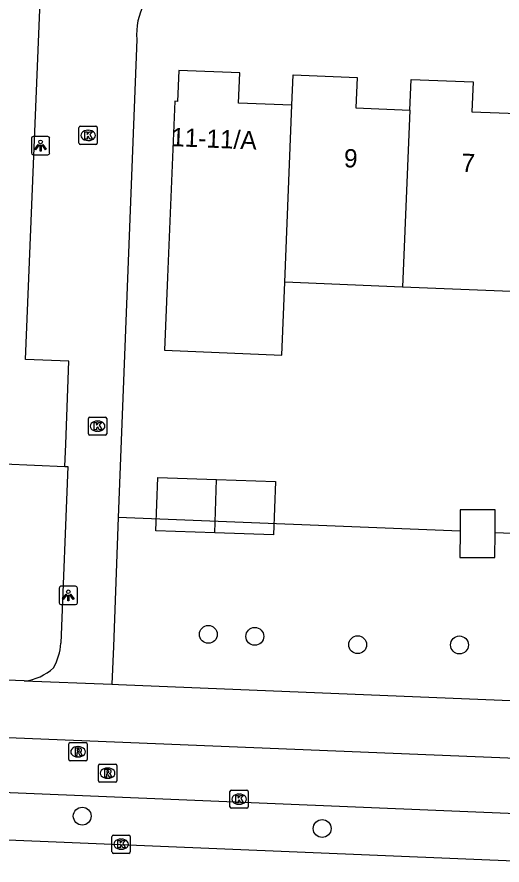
# Model space of a CAD drawing. Extents: x 160732 to 162105, y 387428 to 388479.
# Drawn here: x 161101.46 to 161128, y 387478.56 to 387524.95 of the extents above; entities that cross this region are included whole.
import ezdxf

# ---------------------------------------------------------------- set-up
doc = ezdxf.new("R2010")
doc.units = 0
for name, color, linetype in [('IMGEO_Boom', 7, 'Continuous'), ('IMGEO_Fietspad_open', 7, 'Continuous'), ('IMGEO_Groenvoorziening', 7, 'Continuous'), ('IMGEO_Kolk', 7, 'Continuous'), ('IMGEO_Lichtpunt', 7, 'Continuous'), ('IMGEO_Pand', 7, 'Continuous'), ('IMGEO_Pand_nummerreeks', 7, 'Continuous'), ('IMGEO_Pand_vergunning_verleend', 7, 'Continuous'), ('IMGEO_Rijbaan_lokaal_gesloten', 7, 'Continuous'), ('IMGEO_Rioolput', 7, 'Continuous'), ('IMGEO_Voetpad_open', 7, 'Continuous')]:
    doc.layers.add(name, color=color, linetype=linetype)

msp = doc.modelspace()

# ---------------------------------------------------------------- linework, layer by layer
at = {"layer": 'IMGEO_Boom'}
for centre in [(161111.928, 387491.176), (161114.47, 387491.066), (161120.1, 387490.611), (161125.67, 387490.598), (161105.028, 387481.234), (161118.157, 387480.553)]:
    msp.add_circle(centre, 0.489, dxfattribs=at)
at = {"layer": 'IMGEO_Fietspad_open'}
for points in [[(160801.558, 387514.26), (160820.517, 387511.401), (160862.38, 387504.81), (160891.554, 387500.319), (160901.233, 387498.754), (160911.562, 387497.191), (160935.793, 387493.329), (160945.905, 387492.112), (160955.896, 387491.483), (160964.882, 387491.216), (161000, 387489.783), (161032.946, 387488.45), (161079.41, 387486.41), (161134.151, 387484.191)], [(161032.863, 387485.379), (161078.213, 387483.477), (161134.039, 387481.162)]]:
    msp.add_lwpolyline(points, dxfattribs=at)
at = {"layer": 'IMGEO_Groenvoorziening'}
for points in [[(161070.371, 387540.152), (161070.05, 387531.608), (161068.211, 387531.677), (161067.968, 387525.152), (161069.806, 387525.083), (161068.983, 387503.133), (161068.831, 387499.085), (161090.674, 387498.116), (161090.78, 387500.95), (161104.081, 387500.36)], [(161125.701, 387496.813), (161107.002, 387497.56)], [(161149.999, 387495.842), (161127.619, 387496.736)]]:
    msp.add_lwpolyline(points, dxfattribs=at)
at = {"layer": 'IMGEO_Kolk'}
for p, q in [((161104.85, 387518.044), (161104.85, 387518.896)), ((161104.925, 387518.97), (161105.777, 387518.97)), ((161105.851, 387518.896), (161105.851, 387518.044)), ((161105.338, 387518.75), (161105.363, 387518.75)), ((161105.777, 387517.97), (161104.925, 387517.97)), ((161105.361, 387518.19), (161105.336, 387518.19)), ((161105.442, 387503.065), (161106.294, 387503.065)), ((161105.367, 387502.139), (161105.367, 387502.991)), ((161105.855, 387502.845), (161105.88, 387502.845)), ((161106.368, 387502.991), (161106.368, 387502.139)), ((161105.878, 387502.285), (161105.853, 387502.285)), ((161106.294, 387502.065), (161105.442, 387502.065)), ((161113.186, 387482.662), (161114.038, 387482.662)), ((161113.111, 387481.736), (161113.111, 387482.588)), ((161113.599, 387482.442), (161113.624, 387482.442)), ((161114.112, 387482.588), (161114.112, 387481.736)), ((161113.622, 387481.882), (161113.597, 387481.882)), ((161114.038, 387481.662), (161113.186, 387481.662)), ((161106.656, 387479.272), (161106.656, 387480.124)), ((161106.731, 387480.198), (161107.583, 387480.198)), ((161107.144, 387479.978), (161107.169, 387479.978)), ((161107.657, 387480.124), (161107.657, 387479.272)), ((161107.167, 387479.418), (161107.142, 387479.418)), ((161107.583, 387479.198), (161106.731, 387479.198))]:
    msp.add_line(p, q, dxfattribs=at)
for points in [[(161104.85, 387518.044), (161104.85, 387518.896)], [(161104.925, 387518.97), (161105.777, 387518.97)], [(161105.851, 387518.896), (161105.851, 387518.044)], [(161105.171, 387518.67), (161105.294, 387518.67), (161105.294, 387518.519), (161105.424, 387518.67), (161105.588, 387518.67), (161105.442, 387518.519), (161105.595, 387518.27), (161105.443, 387518.27), (161105.358, 387518.434), (161105.294, 387518.367), (161105.294, 387518.27), (161105.171, 387518.27), (161105.171, 387518.67)], [(161105.777, 387517.97), (161104.925, 387517.97)], [(161105.442, 387503.065), (161106.294, 387503.065)], [(161105.367, 387502.139), (161105.367, 387502.991)], [(161105.688, 387502.765), (161105.811, 387502.765), (161105.811, 387502.614), (161105.941, 387502.765), (161106.105, 387502.765), (161105.959, 387502.614), (161106.112, 387502.365), (161105.96, 387502.365), (161105.875, 387502.529), (161105.811, 387502.462), (161105.811, 387502.365), (161105.688, 387502.365), (161105.688, 387502.765)], [(161106.368, 387502.991), (161106.368, 387502.139)], [(161106.294, 387502.065), (161105.442, 387502.065)], [(161113.186, 387482.662), (161114.038, 387482.662)], [(161113.111, 387481.736), (161113.111, 387482.588)], [(161113.432, 387482.362), (161113.555, 387482.362), (161113.555, 387482.211), (161113.685, 387482.362), (161113.849, 387482.362), (161113.703, 387482.211), (161113.856, 387481.962), (161113.704, 387481.962), (161113.619, 387482.126), (161113.555, 387482.059), (161113.555, 387481.962), (161113.432, 387481.962), (161113.432, 387482.362)], [(161114.112, 387482.588), (161114.112, 387481.736)], [(161114.038, 387481.662), (161113.186, 387481.662)], [(161106.656, 387479.272), (161106.656, 387480.124)], [(161106.731, 387480.198), (161107.583, 387480.198)], [(161106.977, 387479.898), (161107.1, 387479.898), (161107.1, 387479.747), (161107.23, 387479.898), (161107.394, 387479.898), (161107.248, 387479.747), (161107.401, 387479.498), (161107.249, 387479.498), (161107.164, 387479.662), (161107.1, 387479.595), (161107.1, 387479.498), (161106.977, 387479.498), (161106.977, 387479.898)], [(161107.657, 387480.124), (161107.657, 387479.272)], [(161107.583, 387479.198), (161106.731, 387479.198)]]:
    msp.add_lwpolyline(points, dxfattribs=at)
for centre, start, end in [((161104.927, 387518.894), 91.552, 178.448), ((161104.927, 387518.894), 91.552, 178.448), ((161105.775, 387518.894), 1.552, 88.448), ((161105.775, 387518.894), 1.552, 88.448), ((161104.927, 387518.046), 181.552, 268.448), ((161104.927, 387518.046), 181.552, 268.448), ((161105.775, 387518.046), 271.552, 358.448), ((161105.775, 387518.046), 271.552, 358.448), ((161105.444, 387502.989), 91.552, 178.448), ((161105.444, 387502.989), 91.552, 178.448), ((161106.292, 387502.989), 1.552, 88.448), ((161106.292, 387502.989), 1.552, 88.448), ((161105.444, 387502.141), 181.552, 268.448), ((161105.444, 387502.141), 181.552, 268.448), ((161106.292, 387502.141), 271.552, 358.448), ((161106.292, 387502.141), 271.552, 358.448), ((161113.188, 387482.586), 91.552, 178.448), ((161113.188, 387482.586), 91.552, 178.448), ((161114.036, 387482.586), 1.552, 88.448), ((161114.036, 387482.586), 1.552, 88.448), ((161113.188, 387481.738), 181.552, 268.448), ((161113.188, 387481.738), 181.552, 268.448), ((161114.036, 387481.738), 271.552, 358.448), ((161114.036, 387481.738), 271.552, 358.448), ((161106.733, 387480.122), 91.552, 178.448), ((161106.733, 387480.122), 91.552, 178.448), ((161107.581, 387480.122), 1.552, 88.448), ((161107.581, 387480.122), 1.552, 88.448), ((161106.733, 387479.274), 181.552, 268.448), ((161106.733, 387479.274), 181.552, 268.448), ((161107.581, 387479.274), 271.552, 358.448), ((161107.581, 387479.274), 271.552, 358.448)]:
    msp.add_arc(centre, 0.0765, start, end, dxfattribs=at)
for centre, major_axis, ratio, start_param, end_param in [((161105.337, 387518.47), (-0.387, 0.002), 0.722429, 4.712389, 7.853982), ((161105.362, 387518.47), (-0.39, 0.002), 0.717154, 1.570796, 4.712389), ((161105.854, 387502.565), (-0.387, 0.002), 0.722429, 4.712389, 7.853982), ((161105.879, 387502.565), (-0.39, 0.002), 0.717154, 1.570796, 4.712389), ((161113.598, 387482.162), (-0.387, 0.002), 0.722429, 4.712389, 7.853982), ((161113.623, 387482.162), (-0.39, 0.002), 0.717154, 1.570796, 4.712389), ((161107.143, 387479.698), (-0.387, 0.002), 0.722429, 4.712389, 7.853982), ((161107.168, 387479.698), (-0.39, 0.002), 0.717154, 1.570796, 4.712389)]:
    msp.add_ellipse(centre, major_axis=major_axis, ratio=ratio, start_param=start_param, end_param=end_param, dxfattribs=at)
at = {"layer": 'IMGEO_Lichtpunt'}
for p, q in [((161103.151, 387518.409), (161102.343, 387518.409)), ((161103.151, 387518.409), (161102.343, 387518.409)), ((161102.249, 387518.314), (161102.249, 387517.507)), ((161102.249, 387518.314), (161102.249, 387517.507)), ((161103.245, 387517.507), (161103.245, 387518.314)), ((161103.245, 387517.507), (161103.245, 387518.314)), ((161102.343, 387517.413), (161103.151, 387517.413)), ((161102.343, 387517.413), (161103.151, 387517.413)), ((161104.668, 387493.805), (161103.86, 387493.805)), ((161104.668, 387493.805), (161103.86, 387493.805)), ((161103.766, 387493.71), (161103.766, 387492.903)), ((161103.766, 387493.71), (161103.766, 387492.903)), ((161104.762, 387492.903), (161104.762, 387493.71)), ((161104.762, 387492.903), (161104.762, 387493.71)), ((161103.86, 387492.809), (161104.668, 387492.809)), ((161103.86, 387492.809), (161104.668, 387492.809))]:
    msp.add_line(p, q, dxfattribs=at)
for points in [[(161102.623, 387517.978), (161102.662, 387517.95), (161102.474, 387517.688), (161102.436, 387517.715), (161102.623, 387517.978)], [(161102.725, 387517.93), (161102.772, 387517.93), (161102.772, 387517.608), (161102.725, 387517.608), (161102.725, 387517.93)], [(161102.835, 387517.95), (161102.873, 387517.977), (161103.06, 387517.715), (161103.021, 387517.687), (161102.835, 387517.95)], [(161104.14, 387493.374), (161104.179, 387493.346), (161103.991, 387493.084), (161103.953, 387493.111), (161104.14, 387493.374)], [(161104.242, 387493.326), (161104.289, 387493.326), (161104.289, 387493.004), (161104.242, 387493.004), (161104.242, 387493.326)], [(161104.352, 387493.346), (161104.39, 387493.373), (161104.577, 387493.111), (161104.538, 387493.083), (161104.352, 387493.346)]]:
    msp.add_lwpolyline(points, dxfattribs=at)
for centre in [(161102.748, 387518.112), (161104.265, 387493.508)]:
    msp.add_circle(centre, 0.0994, dxfattribs=at)
for centre, start, end in [((161102.343, 387518.314), 90, 180), ((161102.343, 387518.314), 90, 180), ((161103.151, 387518.314), 0, 90), ((161103.151, 387518.314), 0, 90), ((161102.343, 387517.507), 180, 270), ((161102.343, 387517.507), 180, 270), ((161103.151, 387517.507), 270, 0), ((161103.151, 387517.507), 270, 360), ((161103.86, 387493.71), 90, 180), ((161103.86, 387493.71), 90, 180), ((161104.668, 387493.71), 0, 90), ((161104.668, 387493.71), 0, 90), ((161103.86, 387492.903), 180, 270), ((161103.86, 387492.903), 180, 270), ((161104.668, 387492.903), 270, 0), ((161104.668, 387492.903), 270, 360)]:
    msp.add_arc(centre, 0.0946, start, end, dxfattribs=at)
at = {"layer": 'IMGEO_Pand'}
for points in [[(161116.506, 387520.117), (161113.581, 387520.237), (161113.648, 387521.886), (161110.311, 387522.024), (161110.242, 387520.33), (161110.092, 387520.336), (161109.696, 387510.706), (161109.532, 387506.713), (161115.943, 387506.449), (161116.107, 387510.442)], [(161116.506, 387520.117), (161116.574, 387521.781), (161120.071, 387521.637), (161120.003, 387519.978), (161122.95, 387519.857)], [(161122.95, 387519.857), (161123.019, 387521.534), (161126.415, 387521.394), (161126.348, 387519.767), (161129.332, 387519.645)], [(161116.107, 387510.442), (161116.506, 387520.117)], [(161122.95, 387519.857), (161122.551, 387510.177)], [(161122.551, 387510.177), (161116.107, 387510.442)], [(161128.93, 387509.914), (161122.551, 387510.177)], [(161127.619, 387496.736), (161127.624, 387497.988), (161125.706, 387497.995), (161125.701, 387496.813)], [(161125.701, 387496.813), (161125.696, 387495.379), (161127.614, 387495.372), (161127.619, 387496.736)]]:
    msp.add_lwpolyline(points, dxfattribs=at)
at = {"layer": 'IMGEO_Pand_vergunning_verleend'}
for points in [[(161112.279, 387496.736), (161109.059, 387496.847), (161109.16, 387499.758), (161112.379, 387499.647)], [(161112.279, 387496.736), (161112.379, 387499.647)], [(161112.379, 387499.647), (161115.598, 387499.536), (161115.498, 387496.625), (161112.279, 387496.736)]]:
    msp.add_lwpolyline(points, dxfattribs=at)
at = {"layer": 'IMGEO_Rijbaan_lokaal_gesloten'}
msp.add_lwpolyline([(161133.943, 387478.558), (161032.79, 387482.739)], dxfattribs=at)
at = {"layer": 'IMGEO_Rioolput'}
for p, q in [((161104.297, 387484.328), (161104.297, 387485.18)), ((161104.372, 387485.254), (161105.224, 387485.254)), ((161104.785, 387485.034), (161104.81, 387485.034)), ((161105.298, 387485.18), (161105.298, 387484.328)), ((161105.224, 387484.254), (161104.372, 387484.254)), ((161104.808, 387484.474), (161104.783, 387484.474)), ((161105.992, 387484.084), (161106.844, 387484.084)), ((161105.917, 387483.158), (161105.917, 387484.01)), ((161106.405, 387483.864), (161106.43, 387483.864)), ((161106.918, 387484.01), (161106.918, 387483.158)), ((161106.428, 387483.304), (161106.403, 387483.304)), ((161106.844, 387483.084), (161105.992, 387483.084))]:
    msp.add_line(p, q, dxfattribs=at)
for points in [[(161104.297, 387484.328), (161104.297, 387485.18)], [(161104.372, 387485.254), (161105.224, 387485.254)], [(161105.298, 387485.18), (161105.298, 387484.328)], [(161104.886, 387484.952), (161104.634, 387484.954), (161104.634, 387484.554)], [(161104.634, 387484.554), (161104.758, 387484.554), (161104.758, 387484.716), (161104.769, 387484.716)], [(161104.812, 387484.873), (161104.758, 387484.873), (161104.758, 387484.792)], [(161104.758, 387484.792), (161104.81, 387484.792)], [(161104.816, 387484.687), (161104.887, 387484.554), (161105.027, 387484.554), (161104.962, 387484.68)], [(161105.224, 387484.254), (161104.372, 387484.254)], [(161105.992, 387484.084), (161106.844, 387484.084)], [(161105.917, 387483.158), (161105.917, 387484.01)], [(161106.506, 387483.782), (161106.254, 387483.784), (161106.254, 387483.384)], [(161106.432, 387483.703), (161106.378, 387483.703), (161106.378, 387483.622)], [(161106.378, 387483.622), (161106.43, 387483.622)], [(161106.918, 387484.01), (161106.918, 387483.158)], [(161106.254, 387483.384), (161106.378, 387483.384), (161106.378, 387483.546), (161106.389, 387483.546)], [(161106.436, 387483.517), (161106.507, 387483.384), (161106.647, 387483.384), (161106.582, 387483.51)], [(161106.844, 387483.084), (161105.992, 387483.084)]]:
    msp.add_lwpolyline(points, dxfattribs=at)
for centre, radius, start, end in [((161104.374, 387485.178), 0.0765, 91.552, 178.448), ((161104.374, 387485.178), 0.0765, 91.552, 178.448), ((161105.222, 387485.178), 0.0765, 1.552, 88.448), ((161105.222, 387485.178), 0.0765, 1.552, 88.448), ((161104.768, 387484.663), 0.0533, 26.0293, 88.6989), ((161104.794, 387484.981), 0.19, 274.7715, 282.9687), ((161104.818, 387484.777), 0.0964, 77.0061, 93.1865), ((161104.832, 387484.834), 0.0378, 276.6634, 79.6772), ((161104.885, 387484.842), 0.109, 350.3612, 89.416), ((161104.883, 387484.842), 0.112, 277.5842, 350.9817), ((161104.867, 387484.627), 0.108, 29.5134, 73.7905), ((161104.374, 387484.33), 0.0765, 181.552, 268.448), ((161104.374, 387484.33), 0.0765, 181.552, 268.448), ((161105.222, 387484.33), 0.0765, 271.552, 358.448), ((161105.222, 387484.33), 0.0765, 271.552, 358.448), ((161105.994, 387484.008), 0.0765, 91.552, 178.448), ((161105.994, 387484.008), 0.0765, 91.552, 178.448), ((161106.842, 387484.008), 0.0765, 1.552, 88.448), ((161106.842, 387484.008), 0.0765, 1.552, 88.448), ((161106.414, 387483.811), 0.19, 274.7715, 282.9687), ((161106.438, 387483.607), 0.0964, 77.0061, 93.1865), ((161106.452, 387483.664), 0.0378, 276.6634, 79.6772), ((161106.505, 387483.672), 0.109, 350.3612, 89.416), ((161106.503, 387483.672), 0.112, 277.5842, 350.9817), ((161105.994, 387483.16), 0.0765, 181.552, 268.448), ((161105.994, 387483.16), 0.0765, 181.552, 268.448), ((161106.388, 387483.493), 0.0533, 26.0293, 88.6989), ((161106.487, 387483.457), 0.108, 29.5134, 73.7905), ((161106.842, 387483.16), 0.0765, 271.552, 358.448), ((161106.842, 387483.16), 0.0765, 271.552, 358.448)]:
    msp.add_arc(centre, radius, start, end, dxfattribs=at)
for centre, major_axis, ratio, start_param, end_param in [((161104.784, 387484.754), (-0.387, 0.002), 0.722429, 4.712389, 7.853982), ((161104.809, 387484.754), (-0.39, 0.002), 0.717154, 1.570796, 4.712389), ((161106.404, 387483.584), (-0.387, 0.002), 0.722429, 4.712389, 7.853982), ((161106.429, 387483.584), (-0.39, 0.002), 0.717154, 1.570796, 4.712389)]:
    msp.add_ellipse(centre, major_axis=major_axis, ratio=ratio, start_param=start_param, end_param=end_param, dxfattribs=at)
at = {"layer": 'IMGEO_Voetpad_open'}
for points in [[(161104.081, 387500.36), (161104.126, 387501.573), (161104.296, 387506.114), (161101.918, 387506.211), (161102.795, 387527.593)], [(161108.014, 387523.721), (161107.002, 387497.56)], [(161104.081, 387500.36), (161104.237, 387500.35), (161103.862, 387490.688)], [(161107.002, 387497.56), (161106.73, 387490.51), (161106.65, 387488.446)], [(161101.855, 387488.631), (161086.862, 387489.194), (161068.496, 387490.143), (161052.92, 387490.805), (161052.49, 387490.824)], [(161101.855, 387488.631), (161106.65, 387488.446)], [(161106.65, 387488.446), (161107.019, 387488.431), (161134.267, 387487.321)]]:
    msp.add_lwpolyline(points, dxfattribs=at)
for centre, radius, start, end in [((161111.376, 387524.019), 3.376, 116.733, 185.0668), ((161100.724, 387490.912), 3.146, 330.2744, 355.9184), ((161101.629, 387491.27), 2.649, 274.8888, 313.5994)]:
    msp.add_arc(centre, radius, start, end, dxfattribs=at)

# ---------------------------------------------------------------- texts
at = {"layer": 'IMGEO_Pand_nummerreeks'}
for s, rotation, p in [('11-11/A', 357.6509, (161109.877, 387517.887)), ('9', 357.7389, (161119.333, 387516.733)), ('7', 357.7389, (161125.762, 387516.479))]:
    msp.add_text(s, height=1, rotation=rotation, dxfattribs=at).set_placement(p)

doc.saveas('drawing.dxf')
